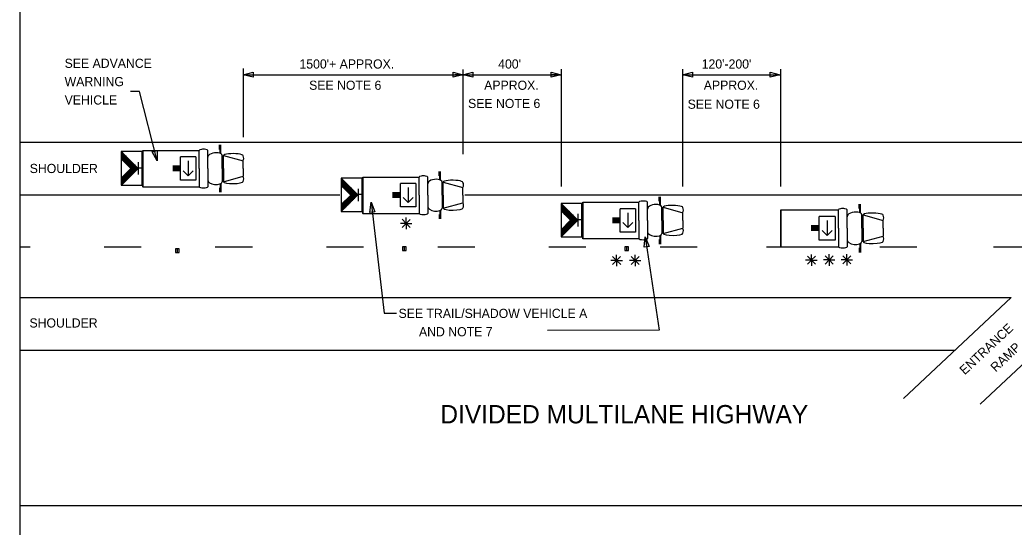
# Model space of a CAD drawing. Extents: x 1806907 to 1812607, y 675071 to 676228.
# Drawn here: x 1810957 to 1811607, y 675403 to 675735 of the extents above; entities that cross this region are included whole.
import ezdxf

# ---------------------------------------------------------------- set-up
doc = ezdxf.new("R2010")
doc.units = 0
for name, color, linetype in [('DSN_DRFT_Named-Boundary', 7, 'Continuous'), ('Level 1', 7, 'Continuous'), ('Working Level 1', 7, 'Continuous')]:
    doc.layers.add(name, color=color, linetype=linetype)

msp = doc.modelspace()

# ---------------------------------------------------------------- linework, layer by layer
at = {"layer": 'DSN_DRFT_Named-Boundary'}
msp.add_lwpolyline([(1810956.68, 675071.2), (1812606.68, 675071.2), (1812606.68, 676121.2), (1810956.68, 676121.2)], close=True, dxfattribs=at)
at = {"layer": 'Level 1'}
msp.add_lwpolyline([(1811365.91, 675593.23), (1811375.1, 675532.18), (1811301.82, 675531.9)], dxfattribs=at)
at = {"layer": 'Working Level 1'}
for p, q in [((1811102.75, 675703.46), (1811102.75, 675658.48)), ((1811102.75, 675699.4), (1811108.31, 675699.4)), ((1811102.75, 675699.4), (1811246.62, 675699.4)), ((1811246.62, 675699.4), (1811241.33, 675699.4)), ((1811246.62, 675702.86), (1811246.62, 675647.41)), ((1811246.62, 675699.4), (1811252.8, 675699.4)), ((1811246.62, 675699.4), (1811310.76, 675699.4)), ((1811310.03, 675699.4), (1811304.74, 675699.4)), ((1811310.76, 675703.1), (1811310.76, 675626.21)), ((1811390.3, 675703.1), (1811390.3, 675626.21)), ((1811390.3, 675699.4), (1811396.48, 675699.4)), ((1811390.3, 675699.4), (1811454.44, 675699.4)), ((1811454.44, 675703.1), (1811454.44, 675626.21)), ((1810956.95, 675655.19), (1811757, 675655.19)), ((1811087.26, 675650.53), (1811087.26, 675653.44)), ((1811087.72, 675647.73), (1811087.72, 675653.44)), ((1811088.11, 675647.73), (1811088.11, 675653.44)), ((1811023.03, 675649.04), (1811033.98, 675638.1)), ((1811037.13, 675649.55), (1811037.13, 675625.78)), ((1811037.23, 675626.05), (1811037.23, 675649.82)), ((1811037.23, 675649.82), (1811037.23, 675626.05)), ((1811037.23, 675649.82), (1811074.02, 675649.82)), ((1811074.02, 675637.93), (1811074.02, 675649.82)), ((1811079.66, 675637.93), (1811079.66, 675649.82)), ((1811089.1, 675637.93), (1811089.1, 675646.49)), ((1811089.89, 675646.49), (1811102.75, 675642.98)), ((1811089.89, 675637.93), (1811089.89, 675646.49)), ((1811023.03, 675644.29), (1811029.31, 675638.03)), ((1811034.35, 675633.98), (1811034.35, 675642.22)), ((1811071.86, 675645.54), (1811061.81, 675645.54)), ((1811061.81, 675630.32), (1811061.81, 675645.54)), ((1811066.83, 675642.96), (1811066.83, 675633.23)), ((1811071.86, 675645.54), (1811071.86, 675630.32)), ((1811102.75, 675637.93), (1811102.75, 675642.98)), ((1811023.03, 675631.77), (1811029.31, 675638.03)), ((1811023.09, 675627.19), (1811033.98, 675638.1)), ((1811036.64, 675638.29), (1811034.29, 675638.29)), ((1811061.81, 675639.45), (1811056.68, 675639.45)), ((1811061.81, 675638.69), (1811056.68, 675638.69)), ((1811061.81, 675637.93), (1811056.68, 675637.93)), ((1811061.81, 675637.17), (1811056.68, 675637.17)), ((1811061.81, 675636.41), (1811056.68, 675636.41)), ((1811066.83, 675633.23), (1811063.53, 675636.53)), ((1811066.83, 675633.23), (1811070.06, 675636.45)), ((1811074.02, 675637.93), (1811074.02, 675626.05)), ((1811079.66, 675637.93), (1811079.66, 675626.05)), ((1811089.1, 675637.93), (1811089.1, 675629.37)), ((1811089.89, 675637.93), (1811089.89, 675629.37)), ((1811102.75, 675637.93), (1811102.75, 675632.89)), ((1811231.12, 675633.12), (1811231.12, 675636.03)), ((1811231.58, 675630.32), (1811231.58, 675636.03)), ((1811231.97, 675630.32), (1811231.97, 675636.03)), ((1811071.86, 675630.32), (1811061.81, 675630.32)), ((1811087.72, 675628.14), (1811087.72, 675622.43)), ((1811088.11, 675628.14), (1811088.11, 675622.43)), ((1811089.89, 675629.37), (1811102.75, 675632.89)), ((1811166.89, 675631.63), (1811177.85, 675620.68)), ((1811166.89, 675626.88), (1811173.17, 675620.62)), ((1811181, 675632.14), (1811181, 675608.37)), ((1811181.09, 675632.41), (1811181.09, 675608.64)), ((1811181.09, 675608.63), (1811181.09, 675632.4)), ((1811181.09, 675632.4), (1811217.89, 675632.4)), ((1811215.73, 675628.13), (1811205.67, 675628.13)), ((1811205.67, 675612.91), (1811205.67, 675628.13)), ((1811215.73, 675628.13), (1811215.73, 675612.91)), ((1811217.89, 675620.52), (1811217.89, 675632.4)), ((1811223.52, 675620.52), (1811223.52, 675632.4)), ((1811232.97, 675620.52), (1811232.97, 675629.08)), ((1811233.75, 675629.08), (1811246.62, 675625.56)), ((1811233.75, 675620.52), (1811233.75, 675629.08)), ((1810956.95, 675620.71), (1811103.21, 675620.71)), ((1811037.23, 675626.05), (1811074.02, 675626.05)), ((1811087.26, 675625.34), (1811087.26, 675622.43)), ((1811102.99, 675620.71), (1811165.94, 675620.71)), ((1811166.89, 675614.35), (1811173.17, 675620.62)), ((1811166.95, 675609.78), (1811177.85, 675620.68)), ((1811180.51, 675620.88), (1811178.15, 675620.88)), ((1811178.22, 675616.56), (1811178.22, 675624.8)), ((1811205.67, 675622.04), (1811200.55, 675622.04)), ((1811205.67, 675621.28), (1811200.55, 675621.28)), ((1811205.67, 675620.52), (1811200.55, 675620.52)), ((1811210.7, 675625.54), (1811210.7, 675615.81)), ((1811217.89, 675620.52), (1811217.89, 675608.64)), ((1811223.52, 675620.52), (1811223.52, 675608.64)), ((1811232.97, 675620.52), (1811232.97, 675611.96)), ((1811233.75, 675620.52), (1811233.75, 675611.96)), ((1811246.62, 675620.52), (1811246.62, 675625.56)), ((1811246.62, 675620.52), (1811246.62, 675615.48)), ((1811247.93, 675620.71), (1811757, 675620.71)), ((1811205.67, 675619.76), (1811200.55, 675619.76)), ((1811205.67, 675619), (1811200.55, 675619)), ((1811210.7, 675615.81), (1811207.39, 675619.12)), ((1811210.7, 675615.81), (1811213.93, 675619.04)), ((1811233.75, 675611.96), (1811246.62, 675615.48)), ((1811310.76, 675615.15), (1811321.72, 675604.21)), ((1811324.87, 675615.66), (1811324.87, 675591.89)), ((1811324.96, 675592.16), (1811324.96, 675615.93)), ((1811324.96, 675615.93), (1811324.96, 675592.16)), ((1811324.96, 675615.93), (1811361.75, 675615.93)), ((1811361.75, 675604.04), (1811361.75, 675615.93)), ((1811367.39, 675604.04), (1811367.39, 675615.93)), ((1811374.99, 675616.64), (1811374.99, 675619.55)), ((1811375.45, 675613.84), (1811375.45, 675619.55)), ((1811375.84, 675613.84), (1811375.84, 675619.55)), ((1811505.76, 675611.73), (1811505.76, 675614.7)), ((1811506.23, 675608.88), (1811506.23, 675614.7)), ((1811506.63, 675608.88), (1811506.63, 675614.7)), ((1811181.09, 675608.64), (1811217.89, 675608.64)), ((1811215.73, 675612.91), (1811205.67, 675612.91)), ((1811231.12, 675607.92), (1811231.12, 675605.02)), ((1811231.58, 675610.73), (1811231.58, 675605.02)), ((1811231.97, 675610.73), (1811231.97, 675605.02)), ((1811310.76, 675610.4), (1811317.04, 675604.14)), ((1811322.08, 675600.09), (1811322.08, 675608.33)), ((1811359.59, 675611.65), (1811349.54, 675611.65)), ((1811349.54, 675596.43), (1811349.54, 675611.65)), ((1811354.56, 675609.07), (1811354.56, 675599.34)), ((1811359.59, 675611.65), (1811359.59, 675596.43)), ((1811376.84, 675604.04), (1811376.84, 675612.6)), ((1811377.62, 675612.6), (1811390.48, 675609.09)), ((1811377.62, 675604.04), (1811377.62, 675612.6)), ((1811390.48, 675604.04), (1811390.48, 675609.09)), ((1811454.71, 675611.01), (1811492.26, 675611.01)), ((1811454.71, 675586.75), (1811454.71, 675611.01)), ((1811454.71, 675611.01), (1811454.71, 675586.76)), ((1811492.26, 675598.88), (1811492.26, 675611.01)), ((1811498.01, 675598.88), (1811498.01, 675611.01)), ((1811507.64, 675598.88), (1811507.64, 675607.62)), ((1811508.45, 675607.62), (1811521.57, 675604.03)), ((1811508.45, 675598.88), (1811508.45, 675607.62)), ((1811209.45, 675602.09), (1811205.69, 675602.09)), ((1811209.45, 675602.09), (1811206.79, 675604.75)), ((1811209.45, 675602.09), (1811206.79, 675599.43)), ((1811209.39, 675602.04), (1811212.05, 675604.7)), ((1811209.45, 675602.09), (1811209.45, 675605.85)), ((1811209.45, 675602.09), (1811212.11, 675599.43)), ((1811209.45, 675602.09), (1811209.45, 675598.33)), ((1811209.45, 675602.09), (1811213.21, 675602.09)), ((1811310.76, 675597.88), (1811317.04, 675604.14)), ((1811310.82, 675593.3), (1811321.72, 675604.21)), ((1811324.38, 675604.4), (1811322.02, 675604.4)), ((1811349.54, 675605.56), (1811344.41, 675605.56)), ((1811349.54, 675604.8), (1811344.41, 675604.8)), ((1811349.54, 675604.04), (1811344.41, 675604.04)), ((1811349.54, 675603.28), (1811344.41, 675603.28)), ((1811349.54, 675602.52), (1811344.41, 675602.52)), ((1811354.56, 675599.34), (1811351.26, 675602.64)), ((1811354.56, 675599.34), (1811357.79, 675602.56)), ((1811361.75, 675604.04), (1811361.75, 675592.16)), ((1811367.39, 675604.04), (1811367.39, 675592.16)), ((1811376.84, 675604.04), (1811376.84, 675595.48)), ((1811377.62, 675604.04), (1811377.62, 675595.48)), ((1811390.48, 675604.04), (1811390.48, 675599)), ((1811490.05, 675606.64), (1811479.79, 675606.64)), ((1811479.79, 675591.12), (1811479.79, 675606.64)), ((1811484.92, 675604.01), (1811484.92, 675594.08)), ((1811490.05, 675606.64), (1811490.05, 675591.12)), ((1811521.57, 675598.88), (1811521.57, 675604.03)), ((1811359.59, 675596.43), (1811349.54, 675596.43)), ((1811375.45, 675594.25), (1811375.45, 675588.54)), ((1811375.84, 675594.25), (1811375.84, 675588.54)), ((1811377.62, 675595.48), (1811390.48, 675599)), ((1811479.79, 675600.43), (1811474.56, 675600.43)), ((1811479.79, 675599.65), (1811474.56, 675599.65)), ((1811479.79, 675598.88), (1811474.56, 675598.88)), ((1811479.79, 675598.1), (1811474.56, 675598.1)), ((1811479.79, 675597.33), (1811474.56, 675597.33)), ((1811484.92, 675594.08), (1811481.55, 675597.45)), ((1811484.92, 675594.08), (1811488.22, 675597.37)), ((1811492.26, 675598.88), (1811492.26, 675586.76)), ((1811498.01, 675598.88), (1811498.01, 675586.76)), ((1811507.64, 675598.88), (1811507.64, 675590.15)), ((1811508.45, 675598.88), (1811508.45, 675590.15)), ((1811521.57, 675598.88), (1811521.57, 675593.74)), ((1811324.96, 675592.16), (1811361.75, 675592.16)), ((1811374.99, 675591.45), (1811374.99, 675588.54)), ((1811490.05, 675591.12), (1811479.79, 675591.12)), ((1811506.23, 675588.89), (1811506.23, 675583.06)), ((1811506.63, 675588.89), (1811506.63, 675583.06)), ((1811508.45, 675590.15), (1811521.57, 675593.74)), ((1811060.89, 675585.47), (1811058.46, 675585.47)), ((1811058.46, 675585.47), (1811058.46, 675583.04)), ((1811058.46, 675583.04), (1811060.89, 675583.04)), ((1811059.68, 675585.47), (1811059.67, 675583.04)), ((1811060.89, 675583.04), (1811060.89, 675585.47)), ((1811209.43, 675586.69), (1811207, 675586.69)), ((1811207, 675586.69), (1811207, 675584.26)), ((1811207, 675584.26), (1811209.43, 675584.26)), ((1811208.22, 675586.69), (1811208.22, 675584.26)), ((1811209.43, 675584.26), (1811209.43, 675586.69)), ((1811347.17, 675577.73), (1811347.17, 675581.5)), ((1811352.48, 675586.69), (1811352.47, 675584.26)), ((1811352.47, 675584.26), (1811354.9, 675584.26)), ((1811354.9, 675586.69), (1811352.48, 675586.69)), ((1811353.7, 675586.69), (1811353.69, 675584.26)), ((1811354.9, 675584.26), (1811354.9, 675586.69)), ((1811359.34, 675577.73), (1811359.34, 675581.5)), ((1811454.71, 675586.76), (1811492.26, 675586.76)), ((1811474.62, 675577.97), (1811474.62, 675581.73)), ((1811486.24, 675578.13), (1811486.24, 675581.89)), ((1811497.77, 675578.21), (1811497.77, 675581.97)), ((1811505.76, 675586.03), (1811505.76, 675583.06)), ((1811347.17, 675577.73), (1811343.4, 675577.73)), ((1811347.17, 675577.73), (1811344.51, 675580.39)), ((1811347.17, 675577.73), (1811344.51, 675575.07)), ((1811347.1, 675577.68), (1811349.77, 675580.34)), ((1811347.17, 675577.73), (1811349.83, 675575.07)), ((1811347.17, 675577.73), (1811347.17, 675573.97)), ((1811347.17, 675577.73), (1811350.93, 675577.73)), ((1811359.34, 675577.73), (1811355.57, 675577.73)), ((1811359.34, 675577.73), (1811356.68, 675580.39)), ((1811359.34, 675577.73), (1811356.68, 675575.07)), ((1811359.27, 675577.68), (1811361.94, 675580.34)), ((1811359.34, 675577.73), (1811362, 675575.07)), ((1811359.34, 675577.73), (1811359.34, 675573.97)), ((1811359.34, 675577.73), (1811363.1, 675577.73)), ((1811474.62, 675577.97), (1811470.85, 675577.97)), ((1811474.62, 675577.97), (1811471.96, 675580.63)), ((1811474.62, 675577.97), (1811471.96, 675575.31)), ((1811474.55, 675577.92), (1811477.22, 675580.58)), ((1811474.62, 675577.97), (1811477.28, 675575.31)), ((1811474.62, 675577.97), (1811474.62, 675574.21)), ((1811474.62, 675577.97), (1811478.38, 675577.97)), ((1811486.24, 675578.13), (1811482.47, 675578.13)), ((1811486.24, 675578.13), (1811483.58, 675580.79)), ((1811486.24, 675578.13), (1811483.58, 675575.47)), ((1811486.17, 675578.08), (1811488.84, 675580.74)), ((1811486.24, 675578.13), (1811488.9, 675575.47)), ((1811486.24, 675578.13), (1811486.24, 675574.37)), ((1811486.24, 675578.13), (1811490, 675578.13)), ((1811497.77, 675578.21), (1811494.01, 675578.21)), ((1811497.77, 675578.21), (1811495.11, 675580.87)), ((1811497.77, 675578.21), (1811495.11, 675575.55)), ((1811497.71, 675578.16), (1811500.37, 675580.82)), ((1811497.77, 675578.21), (1811500.43, 675575.55)), ((1811497.77, 675578.21), (1811497.77, 675574.45)), ((1811497.77, 675578.21), (1811501.53, 675578.21)), ((1810956.95, 675553.49), (1811605.29, 675553.49)), ((1811605.29, 675553.49), (1811534.77, 675487.54)), ((1811659.41, 675553.49), (1811584.93, 675483.84)), ((1810956.95, 675519), (1811568.42, 675519)), ((1810956.95, 675417.33), (1811756.4, 675417.33))]:
    msp.add_line(p, q, dxfattribs=at)
for points in [[(1811109.24, 675697.77), (1811102.74, 675699.4), (1811109.24, 675701.02)], [(1811240.12, 675701.02), (1811246.62, 675699.4), (1811240.12, 675697.77)], [(1811253.12, 675697.77), (1811246.62, 675699.4), (1811253.12, 675701.02)], [(1811304.26, 675701.02), (1811310.76, 675699.4), (1811304.26, 675697.77)], [(1811396.8, 675697.77), (1811390.3, 675699.4), (1811396.8, 675701.02)], [(1811447.67, 675701.02), (1811454.17, 675699.4), (1811447.67, 675697.77)], [(1811023.03, 675649.04), (1811023.03, 675627.19), (1811036.68, 675627.19), (1811036.68, 675649.04)], [(1811046.43, 675649.76), (1811046.45, 675643.06), (1811043.27, 675648.96)], [(1811166.89, 675631.63), (1811166.89, 675609.78), (1811180.55, 675609.78), (1811180.55, 675631.63)], [(1811185.65, 675609.22), (1811186.49, 675615.87), (1811188.88, 675609.6)], [(1811310.76, 675615.15), (1811310.76, 675593.3), (1811324.42, 675593.3), (1811324.42, 675615.15)], [(1811365.27, 675586.56), (1811365.91, 675593.23), (1811368.48, 675587.04)]]:
    msp.add_lwpolyline(points, close=True, dxfattribs=at)
for points in [[(1811046.45, 675643.06), (1811034.92, 675688.5), (1811029.15, 675688.5)], [(1811023.03, 675648.53), (1811028.81, 675638.52)], [(1811023.03, 675647.67), (1811027.66, 675639.63)], [(1811023.03, 675646.81), (1811026.52, 675640.76)], [(1811023.52, 675648.56), (1811031.17, 675635.29)], [(1811024.68, 675647.38), (1811031.48, 675635.61)], [(1811025.86, 675646.22), (1811031.8, 675635.93)], [(1811023.03, 675645.95), (1811025.37, 675641.88)], [(1811023.03, 675645.08), (1811024.23, 675643.01)], [(1811023.03, 675644.22), (1811023.09, 675644.13)], [(1811027.04, 675645.03), (1811032.12, 675636.23)], [(1811028.21, 675643.86), (1811032.43, 675636.55)], [(1811029.38, 675642.68), (1811032.76, 675636.85)], [(1811030.56, 675641.51), (1811033.08, 675637.15)], [(1811031.74, 675640.35), (1811033.37, 675637.51)], [(1811024.43, 675633.17), (1811026.11, 675630.27)], [(1811024.75, 675633.49), (1811026.43, 675630.57)], [(1811025.07, 675633.8), (1811026.75, 675630.89)], [(1811025.38, 675634.12), (1811027.06, 675631.2)], [(1811025.7, 675634.43), (1811027.38, 675631.52)], [(1811026.02, 675634.75), (1811027.7, 675631.83)], [(1811026.33, 675635.07), (1811028.01, 675632.15)], [(1811026.64, 675635.38), (1811028.32, 675632.46)], [(1811026.96, 675635.7), (1811028.65, 675632.77)], [(1811027.28, 675636.01), (1811028.96, 675633.09)], [(1811027.59, 675636.32), (1811029.27, 675633.41)], [(1811027.91, 675636.64), (1811029.59, 675633.72)], [(1811028.22, 675636.95), (1811029.91, 675634.04)], [(1811028.54, 675637.26), (1811030.22, 675634.35)], [(1811028.85, 675637.59), (1811030.54, 675634.67)], [(1811029.17, 675637.9), (1811030.86, 675634.98)], [(1811032.82, 675639.28), (1811033.67, 675637.81)], [(1811023.03, 675631.3), (1811024.54, 675628.69)], [(1811023.03, 675630.44), (1811024.22, 675628.37)], [(1811023.03, 675629.58), (1811023.9, 675628.06)], [(1811023.03, 675628.71), (1811023.59, 675627.75)], [(1811023.03, 675627.86), (1811023.27, 675627.44)], [(1811023.17, 675631.91), (1811024.85, 675629.01)], [(1811023.49, 675632.23), (1811025.17, 675629.32)], [(1811023.81, 675632.54), (1811025.48, 675629.63)], [(1811024.12, 675632.86), (1811025.8, 675629.94)], [(1811166.89, 675631.12), (1811172.67, 675621.11)], [(1811166.89, 675630.26), (1811171.53, 675622.22)], [(1811166.89, 675629.4), (1811170.39, 675623.34)], [(1811166.89, 675628.53), (1811169.24, 675624.47)], [(1811166.89, 675627.67), (1811168.1, 675625.59)], [(1811166.89, 675626.81), (1811166.95, 675626.72)], [(1811167.38, 675631.15), (1811175.03, 675617.88)], [(1811168.55, 675629.97), (1811175.35, 675618.19)], [(1811169.73, 675628.8), (1811175.67, 675618.51)], [(1811170.9, 675627.62), (1811175.98, 675618.82)], [(1811172.07, 675626.45), (1811176.3, 675619.14)], [(1811172.71, 675620.17), (1811174.41, 675617.25)], [(1811173.04, 675620.49), (1811174.72, 675617.57)], [(1811173.25, 675625.27), (1811176.62, 675619.43)], [(1811174.42, 675624.1), (1811176.95, 675619.73)], [(1811175.61, 675622.94), (1811177.24, 675620.1)], [(1811176.69, 675621.86), (1811177.53, 675620.4)], [(1811166.89, 675613.89), (1811168.4, 675611.28)], [(1811167.04, 675614.5), (1811168.72, 675611.6)], [(1811167.36, 675614.82), (1811169.03, 675611.9)], [(1811167.67, 675615.13), (1811169.34, 675612.22)], [(1811167.99, 675615.45), (1811169.67, 675612.53)], [(1811168.3, 675615.76), (1811169.98, 675612.85)], [(1811168.62, 675616.07), (1811170.29, 675613.16)], [(1811168.93, 675616.39), (1811170.61, 675613.48)], [(1811169.25, 675616.71), (1811170.93, 675613.79)], [(1811169.57, 675617.02), (1811171.24, 675614.1)], [(1811169.88, 675617.34), (1811171.56, 675614.42)], [(1811170.2, 675617.66), (1811171.88, 675614.74)], [(1811170.5, 675617.96), (1811172.19, 675615.05)], [(1811170.83, 675618.28), (1811172.51, 675615.36)], [(1811171.14, 675618.6), (1811172.82, 675615.68)], [(1811171.45, 675618.91), (1811173.14, 675615.99)], [(1811171.77, 675619.23), (1811173.46, 675616.31)], [(1811172.09, 675619.54), (1811173.77, 675616.63)], [(1811172.41, 675619.85), (1811174.09, 675616.94)], [(1811186.49, 675615.87), (1811195.12, 675543.27), (1811203.03, 675543.27)], [(1811310.76, 675614.64), (1811316.54, 675604.63)], [(1811310.76, 675613.78), (1811315.39, 675605.74)], [(1811311.25, 675614.67), (1811318.9, 675601.4)], [(1811166.89, 675613.03), (1811168.08, 675610.96)], [(1811166.89, 675612.17), (1811167.77, 675610.65)], [(1811166.89, 675611.3), (1811167.46, 675610.34)], [(1811166.89, 675610.44), (1811167.13, 675610.03)], [(1811310.76, 675612.92), (1811314.25, 675606.87)], [(1811310.76, 675612.06), (1811313.11, 675607.99)], [(1811310.76, 675611.19), (1811311.96, 675609.12)], [(1811310.76, 675610.33), (1811310.82, 675610.24)], [(1811312.42, 675613.49), (1811319.22, 675601.72)], [(1811313.59, 675612.33), (1811319.53, 675602.04)], [(1811314.77, 675611.14), (1811319.85, 675602.34)], [(1811315.94, 675609.97), (1811320.16, 675602.66)], [(1811317.11, 675608.79), (1811320.49, 675602.96)], [(1811318.29, 675607.62), (1811320.81, 675603.26)], [(1811313.75, 675600.86), (1811315.43, 675597.94)], [(1811314.06, 675601.18), (1811315.74, 675598.26)], [(1811314.37, 675601.49), (1811316.06, 675598.57)], [(1811314.69, 675601.81), (1811316.38, 675598.88)], [(1811315.01, 675602.12), (1811316.69, 675599.2)], [(1811315.32, 675602.43), (1811317.01, 675599.52)], [(1811315.64, 675602.75), (1811317.32, 675599.83)], [(1811315.95, 675603.06), (1811317.64, 675600.15)], [(1811316.27, 675603.37), (1811317.95, 675600.46)], [(1811316.58, 675603.7), (1811318.28, 675600.78)], [(1811316.9, 675604.01), (1811318.59, 675601.09)], [(1811319.47, 675606.46), (1811321.1, 675603.62)], [(1811320.55, 675605.39), (1811321.4, 675603.92)], [(1811310.76, 675597.41), (1811312.27, 675594.8)], [(1811310.76, 675596.55), (1811311.95, 675594.48)], [(1811310.76, 675595.69), (1811311.64, 675594.17)], [(1811310.76, 675594.82), (1811311.32, 675593.86)], [(1811310.91, 675598.02), (1811312.58, 675595.12)], [(1811311.22, 675598.34), (1811312.9, 675595.43)], [(1811311.54, 675598.65), (1811313.21, 675595.74)], [(1811311.86, 675598.97), (1811313.53, 675596.05)], [(1811312.17, 675599.28), (1811313.85, 675596.38)], [(1811312.48, 675599.6), (1811314.16, 675596.68)], [(1811312.8, 675599.91), (1811314.48, 675597)], [(1811313.12, 675600.23), (1811314.8, 675597.31)], [(1811313.43, 675600.54), (1811315.11, 675597.63)], [(1811310.76, 675593.97), (1811311, 675593.55)], [(1810956.95, 675586.72), (1810963.31, 675586.72)], [(1811011.81, 675586.72), (1811036.07, 675586.72)], [(1811084.57, 675586.72), (1811108.82, 675586.72)], [(1811157.32, 675586.72), (1811181.57, 675586.72)], [(1811230.07, 675586.72), (1811254.33, 675586.72)], [(1811302.83, 675586.72), (1811327.08, 675586.72)], [(1811375.58, 675586.72), (1811399.84, 675586.72)], [(1811445.33, 675586.72), (1811469.59, 675586.72)], [(1811519.41, 675586.72), (1811543.66, 675586.72)], [(1811593.85, 675586.72), (1811618.1, 675586.72)]]:
    msp.add_lwpolyline(points, dxfattribs=at)
for centre, radius, start, end in [((1811099.6, 675644.66), 3.57, 331.88006, 28.11991), ((1811099.6, 675631.21), 3.57, 331.88008, 28.11994), ((1811243.47, 675627.25), 3.57, 331.88006, 28.11991), ((1811243.47, 675613.8), 3.57, 331.88008, 28.11994), ((1811387.34, 675610.77), 3.57, 331.88006, 28.11991), ((1811518.36, 675605.75), 3.64, 331.88006, 28.11991), ((1811387.34, 675597.32), 3.57, 331.88008, 28.11994), ((1811518.36, 675592.02), 3.64, 331.88008, 28.11994)]:
    msp.add_arc(centre, radius, start, end, dxfattribs=at)
for centre, major_axis, ratio, start_param, end_param in [((1811076.84, 675649.82), (2.82, 0), 0.269913, 0, 3.141593), ((1811084.38, 675645.91), (4.72, 0.58), 0.503092, 0, 3.141593), ((1811096.32, 675646.42), (6.43, -0.07), 0.2034, 0, 3.141593), ((1811220.7, 675632.4), (2.82, 0), 0.269913, 0, 3.141593), ((1811084.38, 675629.96), (4.72, -0.58), 0.503092, 3.141593, 6.283185), ((1811096.32, 675629.45), (6.43, 0.07), 0.2034, 3.141593, 6.283185), ((1811228.25, 675628.5), (4.72, 0.58), 0.503092, 0, 3.141593), ((1811240.18, 675629.01), (6.43, -0.07), 0.2034, 0, 3.141593), ((1811076.84, 675626.05), (2.82, 0), 0.269913, 3.141593, 6.283185), ((1811364.57, 675615.93), (2.82, 0), 0.269913, 0, 3.141593), ((1811372.11, 675612.02), (4.72, 0.58), 0.503092, 0, 3.141593), ((1811384.05, 675612.53), (6.43, -0.07), 0.2034, 0, 3.141593), ((1811220.7, 675608.64), (2.82, 0), 0.269913, 3.141593, 6.283185), ((1811228.25, 675612.55), (4.72, -0.58), 0.503092, 3.141593, 6.283185), ((1811240.18, 675612.04), (6.43, 0.07), 0.2034, 3.141593, 6.283185), ((1811495.13, 675611.01), (2.88, 0), 0.269913, 0, 3.141593), ((1811502.82, 675607.02), (4.82, 0.6), 0.503092, 0, 3.141593), ((1811515.01, 675607.54), (6.56, -0.08), 0.2034, 0, 3.141593), ((1811372.11, 675596.07), (4.72, -0.58), 0.503092, 3.141593, 6.283185), ((1811384.05, 675595.56), (6.43, 0.07), 0.2034, 3.141593, 6.283185), ((1811364.57, 675592.16), (2.82, 0), 0.269913, 3.141593, 6.283185), ((1811502.82, 675590.75), (4.82, -0.6), 0.503092, 3.141593, 6.283185), ((1811515.01, 675590.22), (6.56, 0.08), 0.2034, 3.141593, 6.283185), ((1811495.13, 675586.76), (2.88, 0), 0.269913, 3.141593, 6.283185)]:
    msp.add_ellipse(centre, major_axis=major_axis, ratio=ratio, start_param=start_param, end_param=end_param, dxfattribs=at)

# ---------------------------------------------------------------- texts
for s, p in [('SEE ADVANCE ', (1810985.97, 675703.89)), ("1500'+ APPROX.", (1811139.63, 675703.43)), ("400'", (1811269.66, 675703.43)), ("120'-200'", (1811402.81, 675703.43)), ('WARNING ', (1810985.97, 675691.89)), ('SEE NOTE 6', (1811145.94, 675689.52)), ('APPROX.', (1811260.5, 675689.52)), ('APPROX.', (1811404.18, 675689.52)), ('VEHICLE', (1810985.97, 675679.89)), ('SEE NOTE 6', (1811249.94, 675677.58)), ('SEE NOTE 6', (1811393.62, 675677.1)), ('SEE TRAIL/SHADOW VEHICLE A ', (1811204.45, 675540.16)), ('      AND NOTE 7', (1811204.45, 675528.16))]:
    msp.add_text(s, height=6, dxfattribs=at).set_placement(p)
for s, height, rotation, p in [('SHOULDER', 6, 0, (1810963.12, 675635.03)), ('SHOULDER', 6, 0, (1810962.96, 675533.91)), ('ENTRANCE', 6, 43.07908, (1811574.96, 675502.59)), ('RAMP', 6, 43.07908, (1811595.21, 675504.44)), ('DIVIDED MULTILANE HIGHWAY', 12, 0, (1811231.79, 675471.16))]:
    msp.add_text(s, height=height, rotation=rotation, dxfattribs=at).set_placement(p)

doc.saveas('drawing.dxf')
